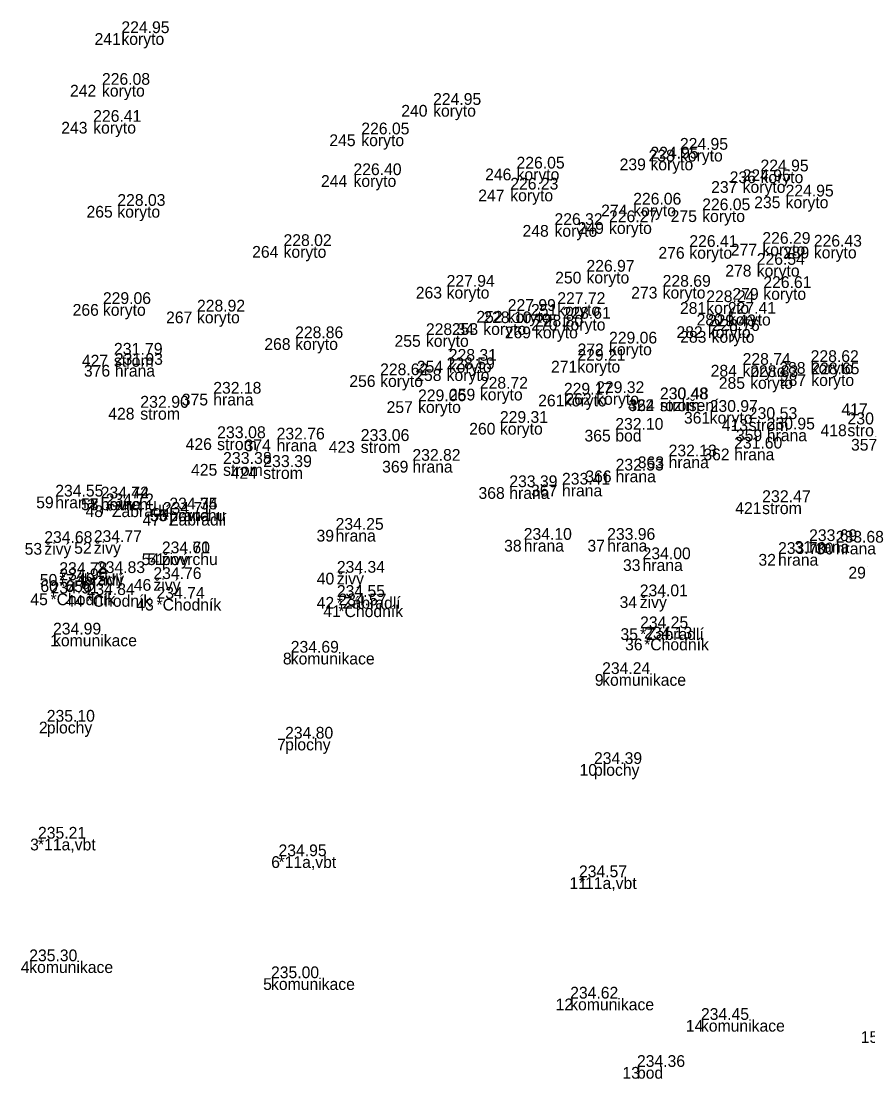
# Model space of a CAD drawing. Extents: x -604224 to 5, y -1156004 to 0.
# Drawn here: x -604224.18 to -604197.18, y -1156002.52 to -1155968.79 of the extents above; entities that cross this region are included whole.
import ezdxf

# ---------------------------------------------------------------- set-up
doc = ezdxf.new("R2010")
doc.units = 0
for name, color, linetype in [('Kód bodu', 7, 'Continuous'), ('Výška bodu', 7, 'Continuous'), ('Značka bodu', 7, 'Continuous'), ('Číslo bodu', 7, 'Continuous')]:
    doc.layers.add(name, color=color, linetype=linetype)

msp = doc.modelspace()

# ---------------------------------------------------------------- linework, layer by layer
at = {"layer": 'Značka bodu'}
for p, q in [((-604220.98, -1155969.17), (-604220.98, -1155969.17)), ((-604221.6, -1155970.82), (-604221.6, -1155970.82)), ((-604211.04, -1155971.46), (-604211.04, -1155971.46)), ((-604221.88, -1155972), (-604221.88, -1155972)), ((-604213.33, -1155972.4), (-604213.33, -1155972.4)), ((-604204.11, -1155973.17), (-604204.11, -1155973.17)), ((-604203.17, -1155972.89), (-604203.17, -1155972.89)), ((-604208.38, -1155973.49), (-604208.38, -1155973.49)), ((-604213.58, -1155973.7), (-604213.58, -1155973.7)), ((-604200.6, -1155973.58), (-604200.6, -1155973.58)), ((-604208.58, -1155974.16), (-604208.58, -1155974.16)), ((-604201.17, -1155973.89), (-604201.17, -1155973.89)), ((-604199.8, -1155974.38), (-604199.8, -1155974.38)), ((-604221.11, -1155974.68), (-604221.11, -1155974.68)), ((-604204.66, -1155974.64), (-604204.66, -1155974.64)), ((-604202.46, -1155974.82), (-604202.46, -1155974.82)), ((-604205.43, -1155975.2), (-604205.43, -1155975.2)), ((-604207.17, -1155975.29), (-604207.17, -1155975.29)), ((-604200.54, -1155975.89), (-604200.54, -1155975.89)), ((-604215.81, -1155975.96), (-604215.81, -1155975.96)), ((-604202.87, -1155975.99), (-604202.87, -1155975.99)), ((-604198.9, -1155975.98), (-604198.9, -1155975.98)), ((-604200.72, -1155976.56), (-604200.72, -1155976.56)), ((-604206.15, -1155976.78), (-604206.15, -1155976.78)), ((-604210.61, -1155977.26), (-604210.61, -1155977.26)), ((-604203.72, -1155977.26), (-604203.72, -1155977.26)), ((-604200.51, -1155977.3), (-604200.51, -1155977.3)), ((-604221.57, -1155977.81), (-604221.57, -1155977.81)), ((-604207.08, -1155977.81), (-604207.08, -1155977.81)), ((-604202.33, -1155977.75), (-604202.33, -1155977.75)), ((-604218.57, -1155978.05), (-604218.57, -1155978.05)), ((-604208.66, -1155978.03), (-604208.66, -1155978.03)), ((-604201.64, -1155978.12), (-604201.64, -1155978.12)), ((-604209.44, -1155978.42), (-604209.44, -1155978.42)), ((-604207.79, -1155978.53), (-604207.79, -1155978.53)), ((-604206.91, -1155978.28), (-604206.91, -1155978.28)), ((-604202.28, -1155978.52), (-604202.28, -1155978.52)), ((-604215.44, -1155978.9), (-604215.44, -1155978.9)), ((-604211.27, -1155978.8), (-604211.27, -1155978.8)), ((-604202.16, -1155978.67), (-604202.16, -1155978.67)), ((-604205.43, -1155979.07), (-604205.43, -1155979.07)), ((-604221.19, -1155979.75), (-604221.19, -1155979.75)), ((-604210.61, -1155979.89), (-604210.61, -1155979.89)), ((-604210.54, -1155979.62), (-604210.54, -1155979.62)), ((-604206.44, -1155979.62), (-604206.44, -1155979.62)), ((-604201.17, -1155979.75), (-604201.17, -1155979.75)), ((-604199, -1155979.66), (-604199, -1155979.66)), ((-604212.73, -1155980.08), (-604212.73, -1155980.08)), ((-604200.93, -1155980.14), (-604200.93, -1155980.14)), ((-604198.98, -1155980.05), (-604198.98, -1155980.05)), ((-604209.55, -1155980.51), (-604209.55, -1155980.51)), ((-604218.05, -1155980.67), (-604218.05, -1155980.67)), ((-604211.52, -1155980.91), (-604211.52, -1155980.91)), ((-604206.87, -1155980.7), (-604206.87, -1155980.7)), ((-604205.84, -1155980.65), (-604205.84, -1155980.65)), ((-604203.81, -1155980.85), (-604203.81, -1155980.85)), ((-604202.22, -1155981.25), (-604202.22, -1155981.25)), ((-604208.91, -1155981.6), (-604208.91, -1155981.6)), ((-604205.23, -1155981.82), (-604205.23, -1155981.82)), ((-604200.4, -1155981.81), (-604200.4, -1155981.81)), ((-604216.03, -1155982.13), (-604216.03, -1155982.13)), ((-604201.44, -1155982.42), (-604201.44, -1155982.42)), ((-604211.7, -1155982.81), (-604211.7, -1155982.81)), ((-604203.53, -1155982.67), (-604203.53, -1155982.67)), ((-604205.22, -1155983.12), (-604205.22, -1155983.12)), ((-604208.61, -1155983.65), (-604208.61, -1155983.65)), ((-604206.93, -1155983.57), (-604206.93, -1155983.57)), ((-604223.09, -1155983.95), (-604223.09, -1155983.95)), ((-604221.64, -1155984.01), (-604221.64, -1155984.01)), ((-604221.64, -1155984.01), (-604221.64, -1155984.01)), ((-604221.48, -1155984.23), (-604221.48, -1155984.23)), ((-604219.66, -1155984.5), (-604219.66, -1155984.5)), ((-604219.45, -1155984.36), (-604219.45, -1155984.36)), ((-604219.45, -1155984.36), (-604219.45, -1155984.36)), ((-604214.15, -1155985.01), (-604214.15, -1155985.01)), ((-604208.15, -1155985.33), (-604208.15, -1155985.33)), ((-604205.49, -1155985.33), (-604205.49, -1155985.33)), ((-604223.44, -1155985.43), (-604223.44, -1155985.43)), ((-604221.86, -1155985.4), (-604221.86, -1155985.4)), ((-604199.05, -1155985.37), (-604199.05, -1155985.37)), ((-604198.2, -1155985.42), (-604198.2, -1155985.42)), ((-604219.69, -1155985.76), (-604219.69, -1155985.76)), ((-604219.69, -1155985.76), (-604219.69, -1155985.76)), ((-604204.36, -1155985.95), (-604204.36, -1155985.95)), ((-604200.04, -1155985.78), (-604200.04, -1155985.78)), ((-604197.19, -1155986.19), (-604197.19, -1155986.19)), ((-604222.96, -1155986.42), (-604222.96, -1155986.42)), ((-604222.96, -1155986.62), (-604222.96, -1155986.62)), ((-604221.76, -1155986.39), (-604221.76, -1155986.39)), ((-604219.96, -1155986.58), (-604219.96, -1155986.58)), ((-604214.11, -1155986.38), (-604214.11, -1155986.38)), ((-604223.24, -1155987.04), (-604223.24, -1155987.04)), ((-604222.09, -1155987.09), (-604222.09, -1155987.09)), ((-604219.86, -1155987.21), (-604219.86, -1155987.21)), ((-604214.11, -1155987.15), (-604214.11, -1155987.15)), ((-604204.45, -1155987.13), (-604204.45, -1155987.13)), ((-604214.06, -1155987.42), (-604214.06, -1155987.42)), ((-604223.16, -1155988.35), (-604223.16, -1155988.35)), ((-604204.44, -1155988.15), (-604204.44, -1155988.15)), ((-604204.31, -1155988.48), (-604204.31, -1155988.48)), ((-604215.58, -1155988.93), (-604215.58, -1155988.93)), ((-604205.65, -1155989.61), (-604205.65, -1155989.61)), ((-604223.36, -1155991.13), (-604223.36, -1155991.13)), ((-604215.76, -1155991.67), (-604215.76, -1155991.67)), ((-604205.91, -1155992.48), (-604205.91, -1155992.48)), ((-604223.64, -1155994.86), (-604223.64, -1155994.86)), ((-604215.97, -1155995.42), (-604215.97, -1155995.42)), ((-604206.39, -1155996.09), (-604206.39, -1155996.09)), ((-604223.92, -1155998.77), (-604223.92, -1155998.77)), ((-604216.21, -1155999.31), (-604216.21, -1155999.31)), ((-604206.67, -1155999.96), (-604206.67, -1155999.96)), ((-604202.5, -1156000.64), (-604202.5, -1156000.64)), ((-604204.54, -1156002.14), (-604204.54, -1156002.14))]:
    msp.add_line(p, q, dxfattribs=at)

# ---------------------------------------------------------------- texts
at = {"layer": 'Kód bodu'}
for s, height, p in [('koryto', 0.375, (-604220.98, -1155969.545)), ('koryto', 0.375, (-604221.6, -1155971.195)), ('koryto', 0.375, (-604211.04, -1155971.835)), ('koryto', 0.375, (-604221.88, -1155972.375)), ('koryto', 0.375, (-604213.33, -1155972.775)), ('koryto', 0.375, (-604204.11, -1155973.545)), ('koryto', 0.375, (-604203.17, -1155973.265)), ('koryto', 0.375, (-604208.38, -1155973.865)), ('koryto', 0.375, (-604213.58, -1155974.075)), ('koryto', 0.375, (-604201.17, -1155974.265)), ('koryto', 0.375, (-604200.6, -1155973.955)), ('koryto', 0.375, (-604208.58, -1155974.535)), ('koryto', 0.375, (-604199.8, -1155974.755)), ('koryto', 0.375, (-604221.11, -1155975.055)), ('koryto', 0.375, (-604204.66, -1155975.015)), ('koryto', 0.375, (-604202.46, -1155975.195)), ('koryto', 0.375, (-604205.43, -1155975.575)), ('koryto', 0.375, (-604207.17, -1155975.665)), ('koryto', 0.375, (-604200.54, -1155976.265)), ('koryto', 0.375, (-604215.81, -1155976.335)), ('koryto', 0.375, (-604202.87, -1155976.365)), ('koryto', 0.375, (-604198.9, -1155976.355)), ('koryto', 0.375, (-604200.72, -1155976.935)), ('koryto', 0.375, (-604206.15, -1155977.155)), ('koryto', 0.375, (-604210.61, -1155977.635)), ('koryto', 0.375, (-604203.72, -1155977.635)), ('koryto', 0.375, (-604200.51, -1155977.675)), ('koryto', 0.375, (-604221.57, -1155978.185)), ('koryto', 0.375, (-604207.08, -1155978.185)), ('koryto', 0.375, (-604202.33, -1155978.125)), ('koryto', 0.375, (-604218.57, -1155978.425)), ('koryto', 0.375, (-604208.66, -1155978.405)), ('koryto', 0.375, (-604201.64, -1155978.495)), ('koryto', 0.375, (-604209.44, -1155978.795)), ('koryto', 0.375, (-604207.79, -1155978.905)), ('koryto', 0.375, (-604206.91, -1155978.655)), ('koryto', 0.375, (-604202.28, -1155978.895)), ('koryto', 0.375, (-604215.44, -1155979.275)), ('koryto', 0.375, (-604211.27, -1155979.175)), ('koryto', 0.375, (-604202.16, -1155979.045)), ('koryto', 0.375, (-604205.43, -1155979.445)), ('strom', 0.38, (-604221.22, -1155979.81)), ('koryto', 0.375, (-604210.54, -1155979.995)), ('koryto', 0.375, (-604206.44, -1155979.995)), ('hrana', 0.375, (-604221.19, -1155980.125)), ('koryto', 0.375, (-604210.61, -1155980.265)), ('koryto', 0.375, (-604201.17, -1155980.125)), ('koryto', 0.375, (-604199, -1155980.035)), ('koryto', 0.375, (-604212.73, -1155980.455)), ('koryto', 0.375, (-604200.93, -1155980.515)), ('koryto', 0.375, (-604198.98, -1155980.425)), ('koryto', 0.375, (-604209.55, -1155980.885)), ('hrana', 0.375, (-604218.05, -1155981.045)), ('koryto', 0.375, (-604211.52, -1155981.285)), ('koryto', 0.375, (-604206.87, -1155981.075)), ('koryto', 0.375, (-604205.84, -1155981.025)), ('strom', 0.38, (-604203.81, -1155981.23)), ('rozlišení', 0.375, (-604203.81, -1155981.225)), ('strom', 0.38, (-604220.38, -1155981.5)), ('koryto', 0.375, (-604202.22, -1155981.625)), ('koryto', 0.375, (-604208.91, -1155981.975)), ('strom', 0.38, (-604200.98, -1155981.86)), ('bod', 0.375, (-604205.23, -1155982.195)), ('hrana', 0.375, (-604200.4, -1155982.185)), ('strom', 0.38, (-604197.83, -1155982.03)), ('strom', 0.38, (-604217.93, -1155982.47)), ('hrana', 0.375, (-604216.03, -1155982.505)), ('strom', 0.38, (-604213.35, -1155982.56)), ('hrana', 0.375, (-604201.44, -1155982.795)), ('strom', 0.38, (-604217.74, -1155983.29)), ('hrana', 0.375, (-604211.7, -1155983.185)), ('hrana', 0.375, (-604203.53, -1155983.045)), ('strom', 0.38, (-604216.46, -1155983.39)), ('hrana', 0.375, (-604205.22, -1155983.495)), ('hrana', 0.375, (-604208.61, -1155984.025)), ('hrana', 0.375, (-604206.93, -1155983.945)), ('hrana', 0.375, (-604223.09, -1155984.325)), ('povrchu', 0.375, (-604221.64, -1155984.385)), ('hrana', 0.375, (-604221.64, -1155984.385)), ('*Zábradlí', 0.375, (-604221.48, -1155984.605)), ('strom', 0.38, (-604200.55, -1155984.51)), ('*Zábradlí', 0.375, (-604219.66, -1155984.875)), ('povrchu', 0.375, (-604219.45, -1155984.735)), ('hrana', 0.375, (-604219.45, -1155984.735)), ('hrana', 0.375, (-604214.15, -1155985.385)), ('hrana', 0.375, (-604208.15, -1155985.705)), ('hrana', 0.375, (-604205.49, -1155985.705)), ('živý', 0.375, (-604223.44, -1155985.805)), ('živý', 0.375, (-604221.86, -1155985.775)), ('hrana', 0.375, (-604199.05, -1155985.745)), ('hrana', 0.375, (-604198.2, -1155985.795)), ('živý', 0.375, (-604219.69, -1155986.135)), ('povrchu', 0.375, (-604219.69, -1155986.135)), ('hrana', 0.375, (-604204.36, -1155986.325)), ('hrana', 0.375, (-604200.04, -1155986.155)), ('*Zábradlí', 0.375, (-604222.96, -1155986.795)), ('*656', 0.375, (-604222.96, -1155986.995)), ('živý', 0.375, (-604221.76, -1155986.765)), ('živý', 0.375, (-604219.96, -1155986.955)), ('živý', 0.375, (-604214.11, -1155986.755)), ('*Chodník', 0.375, (-604223.24, -1155987.415)), ('*Chodník', 0.375, (-604222.09, -1155987.465)), ('*Chodník', 0.375, (-604219.86, -1155987.585)), ('*Zábradlí', 0.375, (-604214.11, -1155987.525)), ('živý', 0.375, (-604204.45, -1155987.505)), ('*Chodník', 0.375, (-604214.06, -1155987.795)), ('komunikace', 0.375, (-604223.16, -1155988.725)), ('*Zábradlí', 0.375, (-604204.44, -1155988.525)), ('*Chodník', 0.375, (-604204.31, -1155988.855)), ('komunikace', 0.375, (-604215.58, -1155989.305)), ('komunikace', 0.375, (-604205.65, -1155989.985)), ('plochy', 0.375, (-604223.36, -1155991.505)), ('plochy', 0.375, (-604215.76, -1155992.045)), ('plochy', 0.375, (-604205.91, -1155992.855)), ('*11a,vbt', 0.375, (-604223.64, -1155995.235)), ('*11a,vbt', 0.375, (-604215.97, -1155995.795)), ('*11a,vbt', 0.375, (-604206.39, -1155996.465)), ('komunikace', 0.375, (-604223.92, -1155999.145)), ('komunikace', 0.375, (-604216.21, -1155999.685)), ('komunikace', 0.375, (-604206.67, -1156000.335)), ('komunikace', 0.375, (-604202.5, -1156001.015)), ('bod', 0.375, (-604204.54, -1156002.515))]:
    msp.add_text(s, height=height, dxfattribs=at).set_placement(p)
at = {"layer": 'Výška bodu'}
for s, height, p in [('224.95', 0.375, (-604220.98, -1155969.17)), ('226.08', 0.375, (-604221.6, -1155970.82)), ('224.95', 0.375, (-604211.04, -1155971.46)), ('226.41', 0.375, (-604221.88, -1155972)), ('226.05', 0.375, (-604213.33, -1155972.4)), ('224.95', 0.375, (-604203.17, -1155972.89)), ('224.95', 0.375, (-604204.11, -1155973.17)), ('226.05', 0.375, (-604208.38, -1155973.49)), ('226.40', 0.375, (-604213.58, -1155973.7)), ('224.95', 0.375, (-604201.17, -1155973.89)), ('224.95', 0.375, (-604200.6, -1155973.58)), ('226.23', 0.375, (-604208.58, -1155974.16)), ('224.95', 0.375, (-604199.8, -1155974.38)), ('228.03', 0.375, (-604221.11, -1155974.68)), ('226.06', 0.375, (-604204.66, -1155974.64)), ('226.05', 0.375, (-604202.46, -1155974.82)), ('226.27', 0.375, (-604205.43, -1155975.2)), ('226.32', 0.375, (-604207.17, -1155975.29)), ('226.29', 0.375, (-604200.54, -1155975.89)), ('228.02', 0.375, (-604215.81, -1155975.96)), ('226.41', 0.375, (-604202.87, -1155975.99)), ('226.43', 0.375, (-604198.9, -1155975.98)), ('226.54', 0.375, (-604200.72, -1155976.56)), ('226.97', 0.375, (-604206.15, -1155976.78)), ('227.94', 0.375, (-604210.61, -1155977.26)), ('228.69', 0.375, (-604203.72, -1155977.26)), ('226.61', 0.375, (-604200.51, -1155977.3)), ('229.06', 0.375, (-604221.57, -1155977.81)), ('227.72', 0.375, (-604207.08, -1155977.81)), ('228.24', 0.375, (-604202.33, -1155977.75)), ('228.92', 0.375, (-604218.57, -1155978.05)), ('227.99', 0.375, (-604208.66, -1155978.03)), ('228.61', 0.375, (-604206.91, -1155978.28)), ('227.41', 0.375, (-604201.64, -1155978.12)), ('228.10', 0.375, (-604209.44, -1155978.42)), ('228.80', 0.375, (-604207.79, -1155978.53)), ('229.43', 0.375, (-604202.28, -1155978.52)), ('228.86', 0.375, (-604215.44, -1155978.9)), ('228.34', 0.375, (-604211.27, -1155978.8)), ('228.76', 0.375, (-604202.16, -1155978.67)), ('229.06', 0.375, (-604205.43, -1155979.07)), ('231.79', 0.38, (-604221.22, -1155979.43)), ('228.31', 0.375, (-604210.54, -1155979.62)), ('229.21', 0.375, (-604206.44, -1155979.62)), ('231.93', 0.375, (-604221.19, -1155979.75)), ('228.59', 0.375, (-604210.61, -1155979.89)), ('228.74', 0.375, (-604201.17, -1155979.75)), ('228.62', 0.375, (-604199, -1155979.66)), ('228.62', 0.375, (-604212.73, -1155980.08)), ('228.83', 0.375, (-604200.93, -1155980.14)), ('228.65', 0.375, (-604198.98, -1155980.05)), ('228.72', 0.375, (-604209.55, -1155980.51)), ('229.32', 0.375, (-604205.84, -1155980.65)), ('232.18', 0.375, (-604218.05, -1155980.67)), ('229.06', 0.375, (-604211.52, -1155980.91)), ('229.17', 0.375, (-604206.87, -1155980.7)), ('230.48', 0.375, (-604203.81, -1155980.85)), ('230.48', 0.38, (-604203.81, -1155980.85)), ('232.90', 0.38, (-604220.38, -1155981.12)), ('230.97', 0.375, (-604202.22, -1155981.25)), ('229.31', 0.375, (-604208.91, -1155981.6)), ('230.53', 0.38, (-604200.98, -1155981.48)), ('230.19', 0.38, (-604197.83, -1155981.65)), ('232.10', 0.375, (-604205.23, -1155981.82)), ('230.95', 0.375, (-604200.4, -1155981.81)), ('233.08', 0.38, (-604217.93, -1155982.09)), ('232.76', 0.375, (-604216.03, -1155982.13)), ('233.06', 0.38, (-604213.35, -1155982.18)), ('232.13', 0.375, (-604203.53, -1155982.67)), ('231.60', 0.375, (-604201.44, -1155982.42)), ('233.38', 0.38, (-604217.74, -1155982.91)), ('233.39', 0.38, (-604216.46, -1155983.01)), ('232.82', 0.375, (-604211.7, -1155982.81)), ('232.53', 0.375, (-604205.22, -1155983.12)), ('233.39', 0.375, (-604208.61, -1155983.65)), ('233.41', 0.375, (-604206.93, -1155983.57)), ('234.55', 0.375, (-604223.09, -1155983.95)), ('234.44', 0.375, (-604221.64, -1155984.01)), ('234.72', 0.375, (-604221.64, -1155984.01)), ('234.72', 0.375, (-604221.48, -1155984.23)), ('234.74', 0.375, (-604219.45, -1155984.36)), ('234.35', 0.375, (-604219.45, -1155984.36)), ('232.47', 0.38, (-604200.55, -1155984.13)), ('234.71', 0.375, (-604219.66, -1155984.5)), ('234.25', 0.375, (-604214.15, -1155985.01)), ('234.10', 0.375, (-604208.15, -1155985.33)), ('233.96', 0.375, (-604205.49, -1155985.33)), ('233.69', 0.375, (-604199.05, -1155985.37)), ('234.68', 0.375, (-604223.44, -1155985.43)), ('234.77', 0.375, (-604221.86, -1155985.4)), ('233.68', 0.375, (-604198.2, -1155985.42)), ('234.60', 0.375, (-604219.69, -1155985.76)), ('234.71', 0.375, (-604219.69, -1155985.76)), ('234.00', 0.375, (-604204.36, -1155985.95)), ('233.70', 0.375, (-604200.04, -1155985.78)), ('234.83', 0.375, (-604221.76, -1155986.39)), ('234.34', 0.375, (-604214.11, -1155986.38)), ('234.78', 0.375, (-604222.96, -1155986.42)), ('234.90', 0.375, (-604222.96, -1155986.62)), ('234.76', 0.375, (-604219.96, -1155986.58)), ('234.91', 0.375, (-604223.24, -1155987.04)), ('234.84', 0.375, (-604222.09, -1155987.09)), ('234.74', 0.375, (-604219.86, -1155987.21)), ('234.55', 0.375, (-604214.11, -1155987.15)), ('234.01', 0.375, (-604204.45, -1155987.13)), ('234.57', 0.375, (-604214.06, -1155987.42)), ('234.99', 0.375, (-604223.16, -1155988.35)), ('234.25', 0.375, (-604204.44, -1155988.15)), ('234.13', 0.375, (-604204.31, -1155988.48)), ('234.69', 0.375, (-604215.58, -1155988.93)), ('234.24', 0.375, (-604205.65, -1155989.61)), ('235.10', 0.375, (-604223.36, -1155991.13)), ('234.80', 0.375, (-604215.76, -1155991.67)), ('234.39', 0.375, (-604205.91, -1155992.48)), ('235.21', 0.375, (-604223.64, -1155994.86)), ('234.95', 0.375, (-604215.97, -1155995.42)), ('234.57', 0.375, (-604206.39, -1155996.09)), ('235.30', 0.375, (-604223.92, -1155998.77)), ('235.00', 0.375, (-604216.21, -1155999.31)), ('234.62', 0.375, (-604206.67, -1155999.96)), ('234.45', 0.375, (-604202.5, -1156000.64)), ('234.36', 0.375, (-604204.54, -1156002.14))]:
    msp.add_text(s, height=height, dxfattribs=at).set_placement(p)
at = {"layer": 'Číslo bodu'}
for s, p in [('241', (-604221.836, -1155969.545)), ('242', (-604222.619, -1155971.195)), ('240', (-604212.056, -1155971.835)), ('243', (-604222.899, -1155972.375)), ('245', (-604214.349, -1155972.775)), ('239', (-604205.093, -1155973.545)), ('238', (-604204.171, -1155973.265)), ('246', (-604209.381, -1155973.865)), ('244', (-604214.616, -1155974.075)), ('236', (-604201.583, -1155973.955)), ('247', (-604209.602, -1155974.535)), ('237', (-604202.174, -1155974.265)), ('235', (-604200.801, -1155974.755)), ('265', (-604222.093, -1155975.055)), ('274', (-604205.682, -1155975.015)), ('275', (-604203.464, -1155975.195)), ('249', (-604206.431, -1155975.575)), ('248', (-604208.189, -1155975.665)), ('277', (-604201.547, -1155976.265)), ('264', (-604216.811, -1155976.335)), ('276', (-604203.856, -1155976.365)), ('289', (-604199.883, -1155976.355)), ('278', (-604201.724, -1155976.935)), ('250', (-604207.148, -1155977.155)), ('263', (-604211.593, -1155977.635)), ('273', (-604204.724, -1155977.635)), ('279', (-604201.496, -1155977.675)), ('266', (-604222.536, -1155978.185)), ('251', (-604207.919, -1155978.185)), ('281', (-604203.169, -1155978.125)), ('267', (-604219.556, -1155978.425)), ('252', (-604209.661, -1155978.405)), ('280', (-604202.638, -1155978.495)), ('253', (-604210.441, -1155978.795)), ('269', (-604208.756, -1155978.905)), ('270', (-604207.911, -1155978.655)), ('282', (-604203.281, -1155978.895)), ('268', (-604216.423, -1155979.275)), ('255', (-604212.271, -1155979.175)), ('283', (-604203.161, -1155979.045)), ('272', (-604206.434, -1155979.445)), ('427', (-604222.242, -1155979.805)), ('376', (-604222.176, -1155980.125)), ('258', (-604211.611, -1155980.265)), ('254', (-604211.559, -1155979.995)), ('271', (-604207.281, -1155979.995)), ('284', (-604202.189, -1155980.125)), ('288', (-604200.001, -1155980.035)), ('256', (-604213.713, -1155980.455)), ('285', (-604201.931, -1155980.515)), ('287', (-604199.984, -1155980.425)), ('259', (-604210.533, -1155980.885)), ('375', (-604219.054, -1155981.045)), ('257', (-604212.524, -1155981.285)), ('261', (-604207.691, -1155981.075)), ('262', (-604206.823, -1155981.025)), ('422', (-604204.829, -1155981.225)), ('364', (-604204.811, -1155981.225)), ('428', (-604221.399, -1155981.495)), ('361', (-604203.041, -1155981.625)), ('417', (-604198.019, -1155981.355)), ('260', (-604209.89, -1155981.975)), ('413', (-604201.836, -1155981.855)), ('365', (-604206.213, -1155982.195)), ('359', (-604201.383, -1155982.185)), ('418', (-604198.686, -1155982.025)), ('426', (-604218.931, -1155982.465)), ('374', (-604217.052, -1155982.505)), ('423', (-604214.369, -1155982.555)), ('357', (-604197.714, -1155982.485)), ('362', (-604202.423, -1155982.795)), ('425', (-604218.759, -1155983.285)), ('369', (-604212.666, -1155983.185)), ('363', (-604204.513, -1155983.045)), ('424', (-604217.496, -1155983.385)), ('366', (-604206.186, -1155983.495)), ('368', (-604209.593, -1155984.025)), ('367', (-604207.916, -1155983.945)), ('59', (-604223.698, -1155984.325)), ('57', (-604222.269, -1155984.385)), ('58', (-604222.266, -1155984.385)), ('48', (-604222.124, -1155984.605)), ('421', (-604201.406, -1155984.505)), ('47', (-604220.307, -1155984.875)), ('55', (-604220.076, -1155984.735)), ('56', (-604220.058, -1155984.735)), ('39', (-604214.758, -1155985.385)), ('38', (-604208.776, -1155985.705)), ('37', (-604206.119, -1155985.705)), ('53', (-604224.066, -1155985.805)), ('52', (-604222.486, -1155985.775)), ('31', (-604199.514, -1155985.745)), ('30', (-604198.823, -1155985.795)), ('54', (-604220.334, -1155986.135)), ('51', (-604220.154, -1155986.135)), ('33', (-604204.986, -1155986.325)), ('32', (-604200.666, -1155986.155)), ('29', (-604197.798, -1155986.565)), ('50', (-604223.583, -1155986.795)), ('60', (-604223.565, -1155986.995)), ('49', (-604222.386, -1155986.765)), ('46', (-604220.586, -1155986.955)), ('40', (-604214.751, -1155986.755)), ('45', (-604223.884, -1155987.415)), ('44', (-604222.751, -1155987.465)), ('43', (-604220.504, -1155987.585)), ('42', (-604214.754, -1155987.525)), ('34', (-604205.094, -1155987.505)), ('41', (-604214.541, -1155987.795)), ('1', (-604223.249, -1155988.725)), ('35', (-604205.066, -1155988.525)), ('36', (-604204.918, -1155988.855)), ('8', (-604215.831, -1155989.305)), ('9', (-604205.883, -1155989.985)), ('2', (-604223.611, -1155991.505)), ('7', (-604216.014, -1155992.045)), ('10', (-604206.371, -1155992.855)), ('3', (-604223.891, -1155995.235)), ('6', (-604216.203, -1155995.795)), ('11', (-604206.691, -1155996.465)), ('4', (-604224.189, -1155999.145)), ('5', (-604216.461, -1155999.685)), ('12', (-604207.134, -1156000.335)), ('14', (-604202.981, -1156001.015)), ('15', (-604197.404, -1156001.375)), ('13', (-604205.004, -1156002.515))]:
    msp.add_text(s, height=0.375, dxfattribs=at).set_placement(p)

doc.saveas('drawing.dxf')
